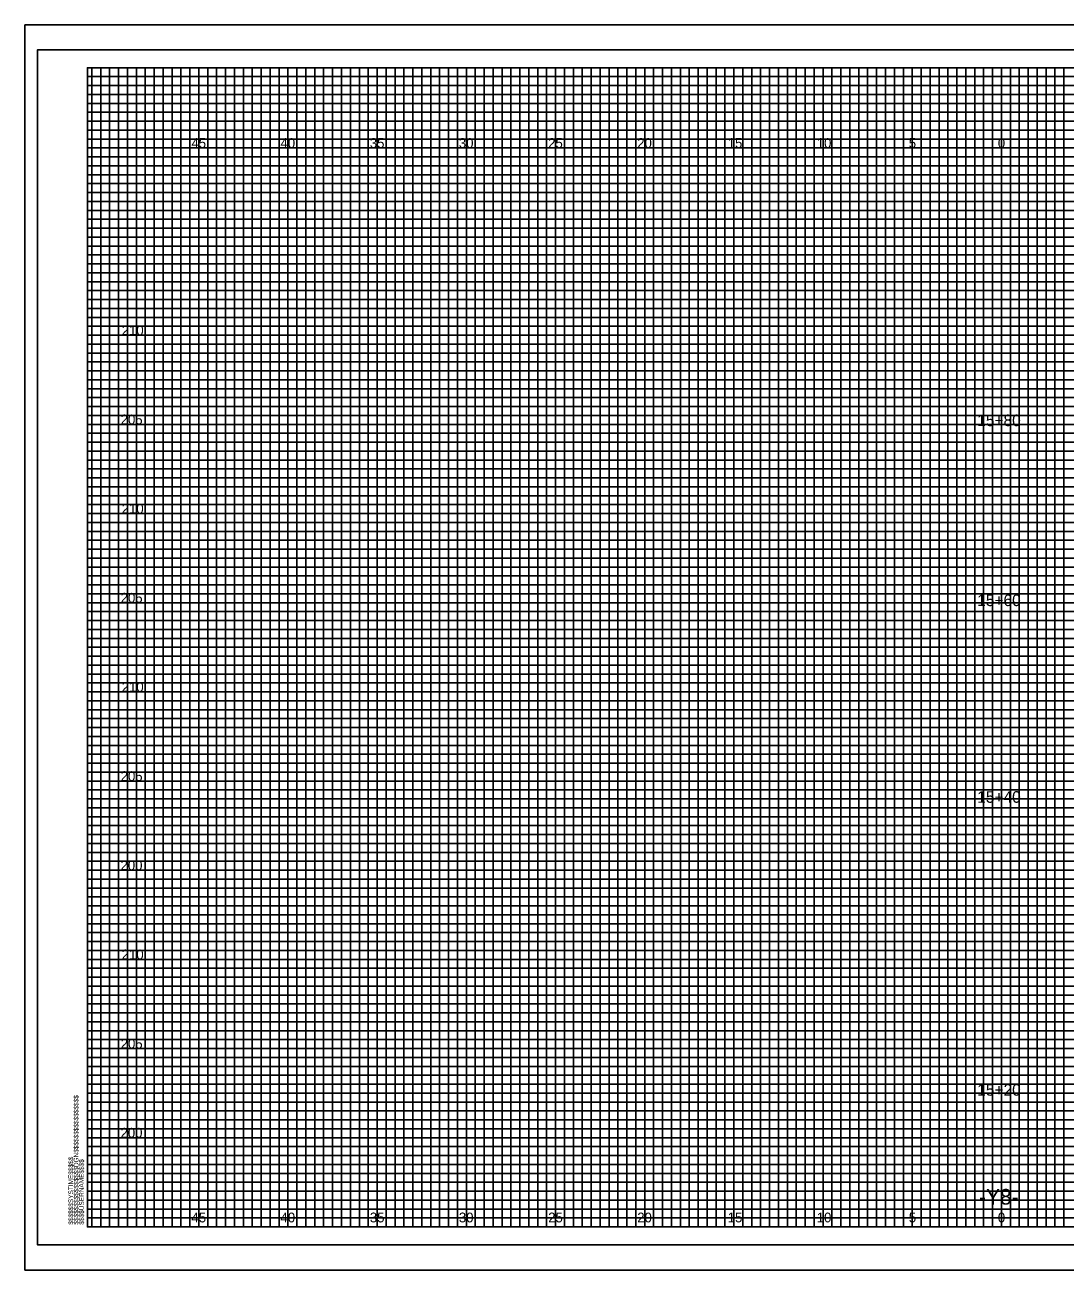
# Model space of a CAD drawing. Extents: x -4 to 103, y -2 to 209.
# Drawn here: x -3.5 to 54.8, y 68.4 to 138.2 of the extents above; entities that cross this region are included whole.
import ezdxf

# ---------------------------------------------------------------- set-up
doc = ezdxf.new("R2010")
doc.units = 0
for name, color, linetype in [('Old_Level_10', 7, 'Continuous'), ('Old_Level_16', 7, 'Continuous'), ('Old_Level_17', 7, 'Continuous'), ('Old_Level_3', 7, 'Continuous'), ('Old_Level_5', 7, 'Continuous'), ('Old_Level_6', 7, 'Continuous'), ('Old_Level_8', 7, 'Continuous'), ('Prop Dimension', 7, 'Continuous'), ('Prop Terminator CELL', 7, 'Continuous'), ('Prop XSC Text', 7, 'Continuous'), ('Typical Curb CELL', 7, 'Continuous')]:
    doc.layers.add(name, color=color, linetype=linetype)

msp = doc.modelspace()

# ---------------------------------------------------------------- linework, layer by layer
at = {"layer": 'Old_Level_10'}
for p, q in [((1.25, 70.825), (1.25, 135.825)), ((3.75, 70.825), (3.75, 135.825)), ((6.25, 70.825), (6.25, 135.825)), ((8.75, 70.825), (8.75, 135.825)), ((11.25, 70.825), (11.25, 135.825)), ((13.75, 70.825), (13.75, 135.825)), ((16.25, 70.825), (16.25, 135.825)), ((18.75, 70.825), (18.75, 135.825)), ((21.25, 70.825), (21.25, 135.825)), ((23.75, 70.825), (23.75, 135.825)), ((26.25, 70.825), (26.25, 135.825)), ((28.75, 70.825), (28.75, 135.825)), ((31.25, 70.825), (31.25, 135.825)), ((33.75, 70.825), (33.75, 135.825)), ((36.25, 70.825), (36.25, 135.825)), ((38.75, 70.825), (38.75, 135.825)), ((41.25, 70.825), (41.25, 135.825)), ((43.75, 70.825), (43.75, 135.825)), ((46.25, 70.825), (46.25, 135.825)), ((48.75, 70.825), (48.75, 135.825)), ((51.25, 70.825), (51.25, 135.825)), ((53.75, 70.825), (53.75, 135.825)), ((0, 133.325), (74.25, 133.325)), ((0, 130.825), (102.5, 130.825)), ((0, 128.325), (102.5, 128.325)), ((0, 125.825), (102.5, 125.825)), ((0, 123.325), (102.5, 123.325)), ((0, 120.825), (102.5, 120.825)), ((0, 118.325), (102.5, 118.325)), ((0, 115.825), (102.5, 115.825)), ((0, 113.325), (102.5, 113.325)), ((0, 110.825), (102.5, 110.825)), ((0, 108.325), (102.5, 108.325)), ((0, 105.825), (102.5, 105.825)), ((0, 103.325), (102.5, 103.325)), ((0, 100.825), (102.5, 100.825)), ((0, 98.325), (102.5, 98.325)), ((0, 95.825), (102.5, 95.825)), ((0, 93.325), (102.5, 93.325)), ((0, 90.825), (102.5, 90.825)), ((0, 88.325), (102.5, 88.325)), ((0, 85.825), (102.5, 85.825)), ((0, 83.325), (102.5, 83.325)), ((0, 80.825), (102.5, 80.825)), ((0, 78.325), (102.5, 78.325)), ((0, 75.825), (102.5, 75.825)), ((0, 73.325), (102.5, 73.325))]:
    msp.add_line(p, q, dxfattribs=at)
at = {"layer": 'Old_Level_17'}
for points in [[(0.25, 70.825), (0.25, 135.825), (0.75, 135.825), (0.75, 70.825), (1.75, 70.825), (1.75, 135.825), (2.25, 135.825), (2.25, 70.825), (2.75, 70.825), (2.75, 135.825), (3.25, 135.825), (3.25, 70.825), (4.25, 70.825), (4.25, 135.825), (4.75, 135.825), (4.75, 70.825), (5.25, 70.825), (5.25, 135.825), (5.75, 135.825), (5.75, 70.825), (6.75, 70.825), (6.75, 135.825), (7.25, 135.825), (7.25, 70.825), (7.75, 70.825), (7.75, 135.825), (8.25, 135.825), (8.25, 70.825), (9.25, 70.825), (9.25, 135.825), (9.75, 135.825), (9.75, 70.825), (10.25, 70.825), (10.25, 135.825), (10.75, 135.825), (10.75, 70.825), (11.75, 70.825), (11.75, 135.825), (12.25, 135.825), (12.25, 70.825), (12.75, 70.825), (12.75, 135.825), (13.25, 135.825), (13.25, 70.825), (14.25, 70.825), (14.25, 135.825), (14.75, 135.825), (14.75, 70.825), (15.75, 70.825), (15.25, 70.825), (15.25, 135.825), (15.75, 135.825), (15.75, 70.825), (16.75, 70.825), (16.75, 135.825), (17.25, 135.825), (17.25, 70.825), (17.75, 70.825), (17.75, 135.825), (18.25, 135.825), (18.25, 70.825), (19.25, 70.825), (19.25, 135.825), (19.75, 135.825), (19.75, 70.825), (20.25, 70.825), (20.25, 135.825), (20.75, 135.825), (20.75, 70.825), (21.75, 70.825), (21.75, 135.825), (22.25, 135.825), (22.25, 70.825), (22.75, 70.825), (22.75, 135.825), (23.25, 135.825), (23.25, 70.825), (24.25, 70.825), (24.25, 135.825), (24.75, 135.825), (24.75, 70.825), (25.25, 70.825), (25.25, 135.825), (25.75, 135.825), (25.75, 70.825), (26.75, 70.825), (26.75, 135.825), (27.25, 135.825), (27.25, 70.825), (27.75, 70.825), (27.75, 135.825), (28.25, 135.825), (28.25, 70.825), (29.25, 70.825), (29.25, 135.825), (29.75, 135.825), (29.75, 70.825), (30.25, 70.825), (30.25, 135.825), (30.75, 135.825), (30.75, 70.825)], [(30.75, 70.825), (31.75, 70.825), (31.75, 135.825), (32.25, 135.825), (32.25, 70.825), (32.75, 70.825), (32.75, 135.825), (33.25, 135.825), (33.25, 70.825), (34.25, 70.825), (34.25, 135.825), (34.75, 135.825), (34.75, 70.825), (35.25, 70.825), (35.25, 135.825), (35.75, 135.825), (35.75, 70.825), (36.75, 70.825), (36.75, 135.825), (37.25, 135.825), (37.25, 70.825), (37.75, 70.825), (37.75, 135.825), (37.75, 70.825)], [(38.25, 135.825), (38.25, 70.825), (39.25, 70.825), (39.25, 135.825), (39.75, 135.825), (39.75, 70.825), (40.25, 70.825), (40.25, 135.825), (40.75, 135.825), (40.75, 70.825), (41.75, 70.825), (41.75, 135.825), (42.25, 135.825), (42.25, 70.825), (42.75, 70.825), (42.75, 135.825), (43.25, 135.825), (43.25, 70.825), (43.75, 70.825), (44.25, 70.825), (44.25, 135.825), (44.75, 135.825), (44.75, 70.825), (45.25, 70.825), (45.25, 135.825), (45.75, 135.825), (45.75, 70.825), (46.75, 70.825), (46.75, 135.825), (47.25, 135.825), (47.25, 70.825), (47.75, 70.825), (47.75, 135.825), (48.25, 135.825), (48.25, 70.825), (49.25, 70.825), (49.25, 135.825), (49.75, 135.825), (49.75, 70.825), (50.25, 70.825), (50.25, 135.825), (50.75, 135.825), (50.75, 70.825), (51.75, 70.825), (51.75, 135.825), (52.25, 135.825), (52.25, 70.825), (52.75, 70.825), (52.75, 135.825), (53.25, 135.825), (53.25, 70.825), (54.25, 70.825), (54.25, 135.825), (54.75, 135.825), (54.75, 70.825), (55.25, 70.825)], [(0, 132.825), (0, 133.825), (74.25, 133.825), (74.25, 134.325), (0, 134.325), (0, 134.825), (74.25, 134.825), (74.25, 135.325), (0, 135.325)], [(102.5, 132.825), (0, 132.825)], [(102.5, 131.825), (0, 131.825), (0, 132.325), (102.5, 132.325)], [(102.5, 130.325), (0, 130.325), (0, 131.325), (102.5, 131.325)], [(102.5, 129.325), (0, 129.325), (0, 129.825), (102.5, 129.825)], [(102.5, 127.825), (0, 127.825), (0, 128.825), (102.5, 128.825)], [(102.5, 126.825), (0, 126.825), (0, 127.325), (102.5, 127.325)], [(102.5, 125.325), (0, 125.325), (0, 126.325), (102.5, 126.325)], [(102.5, 124.325), (0, 124.325), (0, 124.825), (102.5, 124.825)], [(0, 123.825), (102.5, 123.825)], [(102.5, 122.825), (0, 122.825)], [(102.5, 121.825), (0, 121.825), (0, 122.325), (102.5, 122.325)], [(102.5, 120.325), (0, 120.325), (0, 121.325), (102.5, 121.325)], [(102.5, 119.325), (0, 119.325), (0, 119.825), (102.5, 119.825)], [(102.5, 117.825), (0, 117.825), (0, 118.825), (102.5, 118.825)], [(102.5, 116.825), (0, 116.825), (0, 117.325), (102.5, 117.325)], [(102.5, 115.325), (0, 115.325), (0, 116.325), (102.5, 116.325)], [(102.5, 114.325), (0, 114.325), (0, 114.825), (102.5, 114.825)], [(102.5, 112.825), (0, 112.825), (0, 113.825), (102.5, 113.825)], [(102.5, 111.825), (0, 111.825), (0, 112.325), (102.5, 112.325)], [(102.5, 110.325), (0, 110.325), (0, 111.325), (102.5, 111.325)], [(102.5, 109.325), (0, 109.325), (0, 109.825), (102.5, 109.825)], [(102.5, 107.825), (0, 107.825), (0, 108.825), (102.5, 108.825)], [(102.5, 106.825), (0, 106.825), (0, 107.325), (102.5, 107.325)], [(102.5, 105.325), (0, 105.325), (0, 106.325), (102.5, 106.325)], [(102.5, 104.325), (0, 104.325), (0, 104.825), (102.5, 104.825)], [(102.5, 102.825), (0, 102.825), (0, 103.825), (102.5, 103.825)], [(102.5, 101.825), (0, 101.825), (0, 102.325)], [(0, 102.325), (102.5, 102.325)], [(102.5, 100.325), (0, 100.325), (0, 101.325), (102.5, 101.325)], [(102.5, 99.325), (0, 99.325), (0, 99.825), (102.5, 99.825)], [(102.5, 97.825), (0, 97.825), (0, 98.825), (102.5, 98.825)], [(102.5, 96.825), (0, 96.825), (0, 97.325), (102.5, 97.325)], [(102.5, 95.325), (0, 95.325), (0, 96.325), (102.5, 96.325)], [(102.5, 94.325), (0, 94.325), (0, 94.825), (102.5, 94.825)], [(102.5, 92.825), (0, 92.825), (0, 93.825), (102.5, 93.825)], [(102.5, 91.825), (0, 91.825), (0, 92.325), (102.5, 92.325)], [(102.5, 90.325), (0, 90.325), (0, 91.325), (102.5, 91.325)], [(102.5, 89.325), (0, 89.325), (0, 89.825), (102.5, 89.825)], [(102.5, 87.825), (0, 87.825), (0, 88.825), (102.5, 88.825)], [(102.5, 86.825), (0, 86.825), (0, 87.325), (102.5, 87.325)], [(102.5, 85.325), (0, 85.325), (0, 86.325), (102.5, 86.325)], [(102.5, 84.325), (0, 84.325), (0, 84.825), (102.5, 84.825)], [(102.5, 82.825), (0, 82.825), (0, 83.825), (102.5, 83.825)], [(102.5, 81.825), (0, 81.825), (0, 82.325), (102.5, 82.325)], [(102.5, 80.325), (0, 80.325), (0, 81.325), (102.5, 81.325)], [(102.5, 79.325), (0, 79.325), (0, 79.825), (102.5, 79.825)], [(102.5, 77.825), (0, 77.825), (0, 78.825), (102.5, 78.825)], [(102.5, 76.825), (0, 76.825), (0, 77.325), (102.5, 77.325)], [(102.5, 75.325), (0, 75.325), (0, 76.325), (102.5, 76.325)], [(102.5, 74.325), (0, 74.325), (0, 74.825), (102.5, 74.825)], [(102.5, 72.825), (0, 72.825), (0, 73.825), (102.5, 73.825)], [(102.5, 71.825), (0, 71.825), (0, 72.325), (102.5, 72.325)], [(0, 71.325), (102.5, 71.325)]]:
    msp.add_lwpolyline(points, dxfattribs=at)
at = {"layer": 'Old_Level_3'}
for p, q in [((-3.5, 138.225), (103.4, 138.225)), ((-3.5, 138.225), (-3.5, 68.4)), ((-3.5, 68.4), (103.4, 68.4))]:
    msp.add_line(p, q, dxfattribs=at)
at = {"layer": 'Old_Level_5'}
msp.add_lwpolyline([(103.4, 138.225), (-3.5, 138.225), (-3.5, 68.4), (103.4, 68.4)], close=True, dxfattribs=at)
at = {"layer": 'Old_Level_6'}
msp.add_lwpolyline([(102.5, 135.825), (0, 135.825), (0, 70.825), (102.5, 70.825)], close=True, dxfattribs=at)
at = {"layer": 'Old_Level_8'}
for points in [[(1.25, 70.825), (1.25, 135.825), (3.75, 135.825), (3.75, 70.825), (6.25, 70.825), (6.25, 135.825), (8.75, 135.825), (8.75, 70.825), (11.25, 70.825), (11.25, 135.825), (13.75, 135.825), (13.75, 70.825), (16.25, 70.825), (16.25, 135.825), (18.75, 135.825), (18.75, 70.825), (21.25, 70.825), (21.25, 135.825), (23.75, 135.825), (23.75, 70.825), (26.25, 70.825), (26.25, 135.825), (28.75, 135.825), (28.75, 70.825), (31.25, 70.825), (31.25, 135.825), (33.75, 135.825), (33.75, 70.825), (36.25, 70.825), (36.25, 135.825), (38.75, 135.825), (38.75, 70.825), (41.25, 70.825), (41.25, 135.825), (43.75, 135.825), (43.75, 70.825), (46.25, 70.825), (46.25, 135.825), (48.75, 135.825), (48.75, 70.825), (51.25, 70.825), (51.25, 135.825), (53.75, 135.825), (53.75, 70.825)], [(102.5, 130.825), (0, 130.825), (0, 133.325), (74.25, 133.325)], [(102.5, 125.825), (0, 125.825), (0, 128.325), (102.5, 128.325)], [(102.5, 120.825), (0, 120.825), (0, 123.325), (102.5, 123.325)], [(102.5, 115.825), (0, 115.825), (0, 118.325), (102.5, 118.325)], [(102.5, 110.825), (0, 110.825), (0, 113.325), (102.5, 113.325)], [(102.5, 105.825), (0, 105.825), (0, 108.325), (102.5, 108.325)], [(102.5, 100.825), (0, 100.825), (0, 103.325), (102.5, 103.325)], [(102.5, 95.825), (0, 95.825), (0, 98.325), (102.5, 98.325)], [(102.5, 90.825), (0, 90.825), (0, 93.325), (102.5, 93.325)], [(102.5, 85.825), (0, 85.825), (0, 88.325), (102.5, 88.325)], [(102.5, 80.825), (0, 80.825), (0, 83.325), (102.5, 83.325)], [(102.5, 75.825), (0, 75.825), (0, 78.325), (102.5, 78.325)], [(0, 73.325), (102.5, 73.325)]]:
    msp.add_lwpolyline(points, dxfattribs=at)
at = {"layer": 'Typical Curb CELL'}
msp.add_lwpolyline([(103, 136.825), (-2.8, 136.825), (-2.8, 69.825), (103, 69.825)], close=True, dxfattribs=at)

# ---------------------------------------------------------------- texts
at = {"layer": 'Old_Level_16'}
for s, p in [('45', (5.8399, 131.325)), ('40', (10.8313, 131.325)), ('35', (15.8399, 131.325)), ('30', (20.8313, 131.325)), ('25', (25.8399, 131.325)), ('20', (30.8313, 131.325)), ('15', (35.9058, 131.325)), ('10', (40.8971, 131.325)), ('5', (46.0574, 131.325)), ('0', (51.0488, 131.325)), ('0', (51.0488, 131.325)), ('45', (5.8399, 71.075)), ('40', (10.8313, 71.075)), ('35', (15.8399, 71.075)), ('30', (20.8313, 71.075)), ('25', (25.8399, 71.075)), ('20', (30.8313, 71.075)), ('15', (35.9058, 71.075)), ('10', (40.8971, 71.075)), ('5', (46.0574, 71.075)), ('0', (51.0488, 71.075)), ('0', (51.0488, 71.075))]:
    msp.add_text(s, height=0.55, dxfattribs=at).set_placement(p)
at = {"layer": 'Old_Level_6'}
for s, p in [('$$$$$$$$$$$$$$$$DGN$$$$$$$$$$$$$$$$', (-0.5, 70.95)), ('$$$$$$SYSTIME$$$$$', (-0.7973, 70.9497)), ('$$$$USERNAME$$$$', (-0.2, 70.95))]:
    msp.add_text(s, height=0.2625, rotation=90, dxfattribs=at).set_placement(p)
at = {"layer": 'Old_Level_8'}
msp.add_text('040397', height=0.0025, rotation=90, dxfattribs=at).set_placement((-0.0007, 135.8114))
at = {"layer": 'Prop Dimension'}
for s, p in [('210', (1.9296, 120.825)), ('205', (1.8724, 115.825)), ('210', (1.9296, 110.825)), ('205', (1.8724, 105.825)), ('210', (1.9296, 100.825)), ('205', (1.8724, 95.825)), ('200', (1.8638, 90.825)), ('210', (1.9296, 85.825)), ('205', (1.8724, 80.825)), ('200', (1.8638, 75.825))]:
    msp.add_text(s, height=0.55, dxfattribs=at).set_placement(p)
at = {"layer": 'Prop Terminator CELL'}
for s, p in [('15+80', (49.8934, 115.725)), ('15+60', (49.8934, 105.6352)), ('15+40', (49.8934, 94.6051)), ('15+20', (49.8934, 78.1797))]:
    msp.add_text(s, height=0.65, dxfattribs=at).set_placement(p)
at = {"layer": 'Prop XSC Text'}
msp.add_text('-Y8-', height=0.875, dxfattribs=at).set_placement((49.9985, 72.075))

doc.saveas('drawing.dxf')
